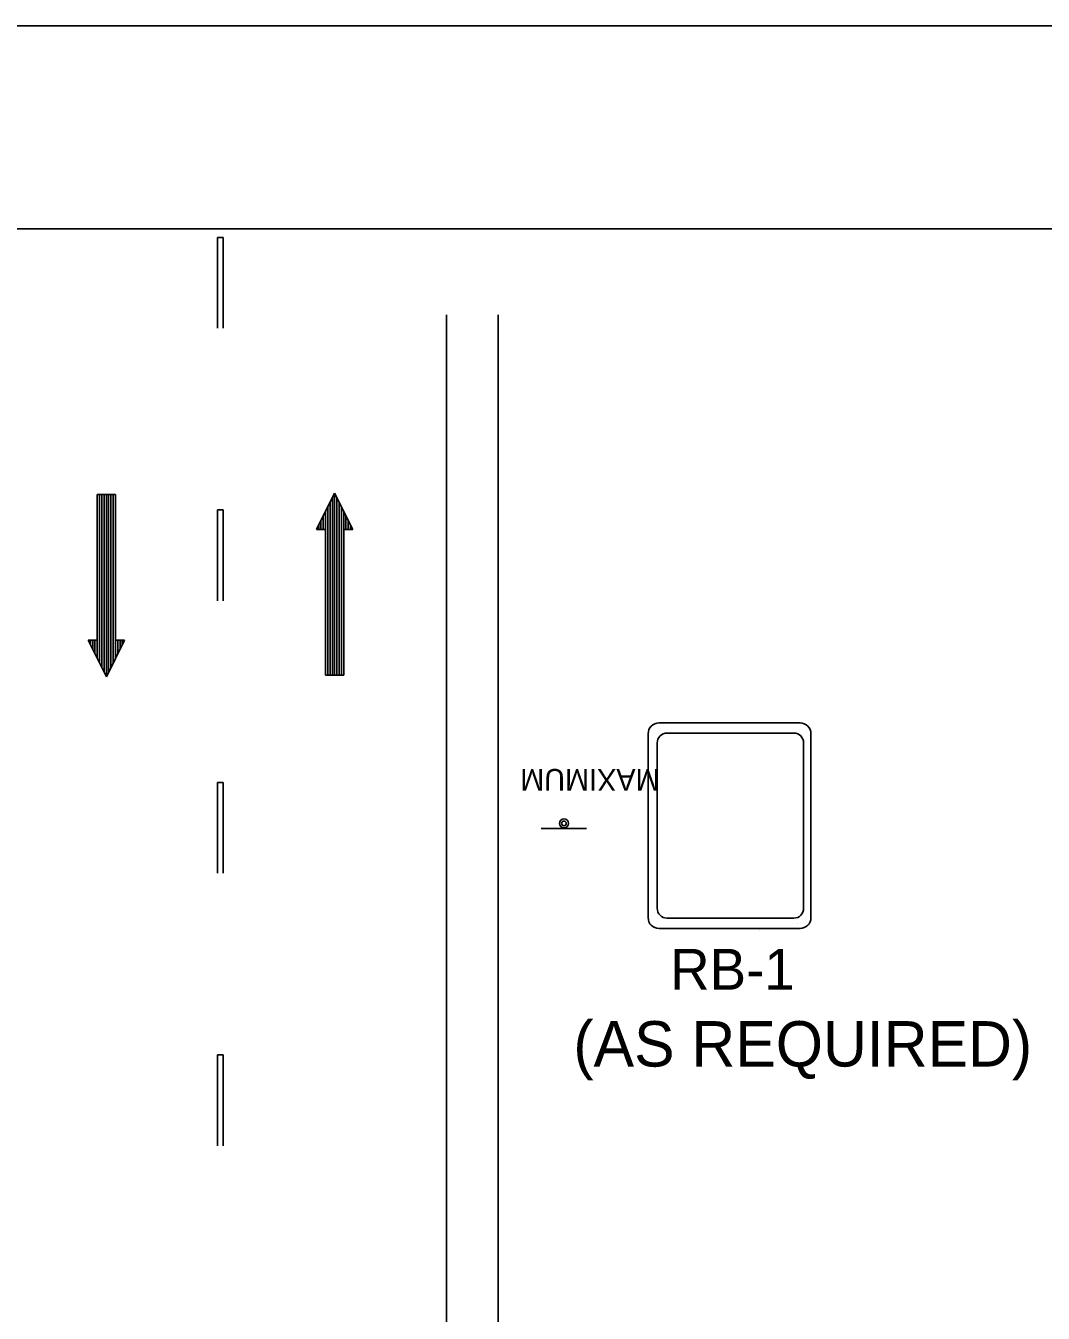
# Model space of a CAD drawing. Extents: x 797 to 1013, y 120 to 399.
# Drawn here: x 851.4 to 905.6, y 330.8 to 399.4 of the extents above; entities that cross this region are included whole.
import ezdxf

# ---------------------------------------------------------------- set-up
doc = ezdxf.new("R2010")
doc.units = 0
for name, color, linetype in [('Level 10', 7, 'Continuous'), ('Level 2', 7, 'Continuous'), ('Level 44', 7, 'Continuous'), ('Level 60', 7, 'Continuous')]:
    doc.layers.add(name, color=color, linetype=linetype)

msp = doc.modelspace()

# ---------------------------------------------------------------- linework, layer by layer
at = {"layer": 'Level 10'}
for p, q in [((873.779, 383.976), (873.779, 135.758)), ((876.533, 383.976), (876.533, 135.758)), ((867.821, 374.484), (866.851, 372.545)), ((867.821, 374.484), (867.821, 364.788)), ((867.821, 374.484), (868.791, 372.545)), ((855.176, 366.648), (855.176, 374.405)), ((856.146, 374.405), (855.176, 374.405)), ((855.176, 365.679), (855.176, 374.405)), ((855.297, 365.436), (855.297, 374.405)), ((855.418, 365.194), (855.418, 374.405)), ((855.54, 364.951), (855.54, 374.405)), ((855.661, 364.709), (855.661, 374.405)), ((855.782, 364.951), (855.782, 374.405)), ((855.903, 365.194), (855.903, 374.405)), ((856.024, 365.436), (856.024, 374.405)), ((856.146, 366.648), (856.146, 374.405)), ((856.146, 365.679), (856.146, 374.405)), ((867.457, 373.757), (867.457, 364.788)), ((867.579, 373.999), (867.579, 364.788)), ((867.7, 374.242), (867.7, 364.788)), ((867.942, 374.242), (867.942, 364.788)), ((868.063, 373.999), (868.063, 364.788)), ((868.185, 373.757), (868.185, 364.788)), ((867.215, 373.272), (867.215, 372.545)), ((867.336, 373.514), (867.336, 364.788)), ((868.306, 373.514), (868.306, 364.788)), ((868.427, 373.272), (868.427, 372.545)), ((866.851, 372.545), (867.336, 372.545)), ((866.973, 372.787), (866.973, 372.545)), ((867.094, 373.03), (867.094, 372.545)), ((867.336, 372.545), (867.336, 364.788)), ((868.306, 372.545), (868.306, 364.788)), ((868.306, 372.545), (868.791, 372.545)), ((868.548, 373.03), (868.548, 372.545)), ((868.669, 372.787), (868.669, 372.545)), ((855.661, 364.709), (854.691, 366.648)), ((855.176, 366.648), (854.691, 366.648)), ((854.812, 366.406), (854.812, 366.648)), ((854.934, 366.163), (854.934, 366.648)), ((855.055, 365.921), (855.055, 366.648)), ((855.661, 364.709), (856.63, 366.648)), ((856.63, 366.648), (856.146, 366.648)), ((856.267, 365.921), (856.267, 366.648)), ((856.388, 366.163), (856.388, 366.648)), ((856.509, 366.406), (856.509, 366.648)), ((867.336, 364.788), (868.306, 364.788))]:
    msp.add_line(p, q, dxfattribs=at)
at = {"layer": 'Level 2'}
for p, q in [((861.589, 388.104), (861.589, 383.266)), ((861.879, 388.104), (861.589, 388.104)), ((861.879, 383.266), (861.879, 388.104)), ((861.589, 373.59), (861.589, 368.752)), ((861.879, 373.59), (861.589, 373.59)), ((861.879, 368.752), (861.879, 373.59)), ((861.589, 359.076), (861.589, 354.238)), ((861.879, 359.076), (861.589, 359.076)), ((861.879, 354.238), (861.879, 359.076)), ((861.589, 344.562), (861.589, 339.724)), ((861.879, 344.562), (861.589, 344.562)), ((861.879, 339.724), (861.879, 344.562))]:
    msp.add_line(p, q, dxfattribs=at)
at = {"layer": 'Level 44'}
for p, q in [((892.616, 362.248), (885.104, 362.248)), ((884.523, 361.668), (884.523, 351.877)), ((892.287, 361.707), (885.527, 361.707)), ((893.195, 351.877), (893.195, 361.668)), ((885.004, 361.185), (885.004, 352.373)), ((892.808, 352.373), (892.808, 361.185)), ((878.821, 356.623), (881.245, 356.623)), ((885.527, 351.85), (892.287, 351.85)), ((892.808, 352.371), (892.808, 352.373)), ((893.195, 351.874), (893.195, 351.877)), ((885.104, 351.295), (892.616, 351.295)), ((890.435, 351.191), (890.435, 351.191)), ((892.483, 351.537), (892.483, 351.537))]:
    msp.add_line(p, q, dxfattribs=at)
for radius in [0.242, 0.121]:
    msp.add_circle((880.037, 356.894), radius, dxfattribs=at)
for centre, radius, start, end in [((885.104, 361.667), 0.58, 90.00001, 180.00001), ((892.615, 361.667), 0.58, 0.00001, 90), ((885.527, 361.184), 0.522, 90.00001, 180.00001), ((892.287, 361.184), 0.522, 0.00001, 90), ((885.104, 351.875), 0.58, 180.00001, 270), ((885.527, 352.371), 0.522, 180.00001, 270), ((892.287, 352.371), 0.522, 270.00001, 0), ((892.615, 351.875), 0.58, 270.00001, 0)]:
    msp.add_arc(centre, radius, start, end, dxfattribs=at)
at = {"layer": 'Level 60'}
for points in [[(1013.16, 399.381), (797.16, 399.381), (797.16, 120.381), (1013.16, 120.381)], [(994.034, 388.572), (807.16, 388.572), (807.16, 131.19), (994.034, 131.19)]]:
    msp.add_lwpolyline(points, close=True, dxfattribs=at)

# ---------------------------------------------------------------- texts
at = {"layer": 'Level 10'}
msp.add_text('RB-1', height=2.1769, rotation=360, dxfattribs=at).set_placement((885.699, 348.033))
msp.add_text('(AS REQUIRED)', height=2.419, dxfattribs=at).set_placement((880.54, 343.942))
at = {"layer": 'Level 44'}
msp.add_text('MAXIMUM', height=1.149, rotation=180, dxfattribs=at).set_placement((885.135, 359.794))

doc.saveas('drawing.dxf')
